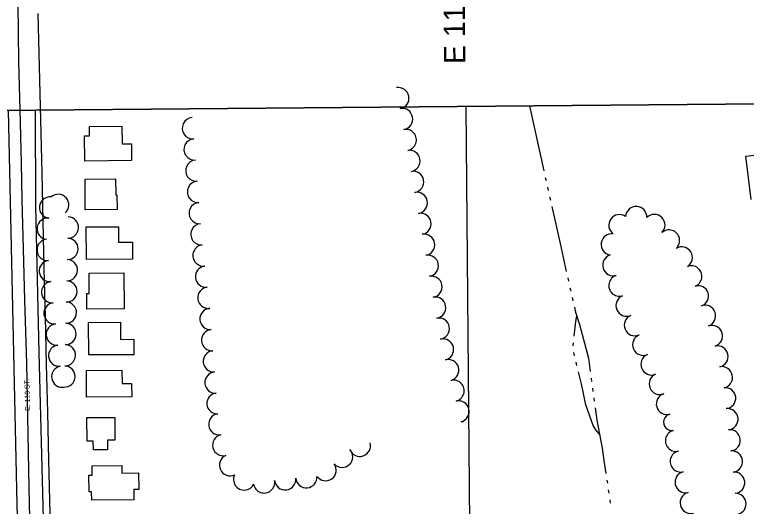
# Model space of a CAD drawing. Extents: x -2233 to 187241, y 4582 to 150524.
# Drawn here: x 111567 to 112255, y 59685 to 60147 of the extents above; entities that cross this region are included whole.
import ezdxf

# ---------------------------------------------------------------- set-up
doc = ezdxf.new("R2010")
doc.units = 0
for name, color, linetype in [('60', 7, 'Continuous'), ('BLDG', 7, 'Continuous'), ('GE_X_CL_2000', 7, 'Continuous'), ('GRID', 7, 'Continuous'), ('ROAD', 7, 'Continuous'), ('ROAD-NAME', 7, 'Continuous'), ('RW_X_Fee_RW', 7, 'Continuous'), ('TREES', 7, 'Continuous'), ('WATER', 7, 'Continuous')]:
    doc.layers.add(name, color=color, linetype=linetype)

msp = doc.modelspace()

# ---------------------------------------------------------------- linework, layer by layer
at = {"layer": '60'}
msp.add_line((109991.08, 60043.59), (114990.89, 60087.23), dxfattribs=at)
at = {"layer": 'BLDG'}
for points in [[(111668, 60025.85), (111676.84, 60025.92), (111676.98, 60010.16), (111632.95, 60009.77), (111632.74, 60033.38), (111637.51, 60033.42), (111637.44, 60042.34), (111667.86, 60042.61)], [(111661.95, 59993.12), (111662.08, 59978), (111663.18, 59978.01), (111663.3, 59964.29), (111633.4, 59964.03), (111633.15, 59992.87)], [(111664.49, 59948.11), (111664.62, 59933.45), (111677.76, 59933.57), (111677.9, 59917.55), (111634.64, 59917.17), (111634.37, 59947.85)], [(111634.91, 59870.71), (111634.79, 59885.28), (111637.15, 59885.3), (111636.98, 59904.32), (111669.71, 59904.61), (111670, 59871.02)], [(111666.41, 59858.38), (111666.5, 59842.18), (111678.99, 59842.26), (111679.08, 59827.79), (111636.69, 59827.54), (111636.5, 59858.2)], [(111667.87, 59813.31), (111667.98, 59800.68), (111677, 59800.76), (111677.11, 59788.23), (111634.63, 59787.86), (111634.41, 59813.02)], [(111661.07, 59768.87), (111661.26, 59747.6), (111654.19, 59747.54), (111654.27, 59738.42), (111641.03, 59738.3), (111640.96, 59746.5), (111635.18, 59746.45), (111634.99, 59768.64)], [(111667.66, 59723.58), (111667.72, 59716.62), (111683.55, 59716.76), (111683.69, 59701.02), (111678.92, 59700.98), (111679, 59691.35), (111639.43, 59691.01), (111639.36, 59699.02), (111636.95, 59698.99), (111636.82, 59714.48), (111639.92, 59714.51), (111639.84, 59723.34)]]:
    msp.add_lwpolyline(points, close=True, dxfattribs=at)
msp.add_lwpolyline([(112259.25, 59973.71), (112254.19, 60014.34), (112277.24, 60017.2)], dxfattribs=at)
at = {"layer": 'GE_X_CL_2000'}
msp.add_lwpolyline([(111569.9, 60158.24), (111570.61, 60102.99), (111571.86, 60058.16), (111573.19, 60008), (111573.92, 59973.34), (111575.04, 59927.2), (111576.39, 59879.05), (111578.02, 59819.9), (111580.22, 59703.14), (111581.06, 59673.72)], dxfattribs=at)
at = {"layer": 'GRID'}
for p, q in [((114990.89, 60087.23), (109991.08, 60043.59)), ((111991.01, 60061.05), (112014.55, 57363.38))]:
    msp.add_line(p, q, dxfattribs=at)
at = {"layer": 'ROAD'}
for points in [[(112373.84, 59543.05), (112169.26, 59540.64), (111865.76, 59535.63), (111696.22, 59533.79), (111617.75, 59532.75), (111611.79, 59532.85), (111605.74, 59534.54), (111600.24, 59539.44), (111597.13, 59546.59), (111596.48, 59553.13), (111594.73, 59649.67), (111590.02, 59829.84), (111586.81, 59967.47), (111586.75, 60057.52)], [(111560.77, 60057.29), (111565.27, 59857.69), (111569.07, 59687.36), (111572.65, 59560.5), (111572.74, 59550.42), (111572.13, 59544.98), (111568.5, 59539.66), (111565.4, 59536.03), (111560.09, 59533.08), (111555.19, 59531.83), (111315.1, 59528.88), (111302.11, 59529.03), (111295.33, 59532.69), (111289.41, 59538.81), (111287.06, 59545.89), (111286.58, 59562.68), (111284.3, 59638.89), (111281.06, 59774.49), (111275.94, 59946.05), (111275.78, 60054.81)]]:
    msp.add_lwpolyline(points, dxfattribs=at)
at = {"layer": 'RW_X_Fee_RW'}
msp.add_lwpolyline([(111603.05, 59562.65), (111600.32, 59678.59), (111599.14, 59728.58), (111598.08, 59773.57), (111597.02, 59818.56), (111595.96, 59863.54), (111594.9, 59908.53), (111593.84, 59953.52), (111592.78, 59998.51), (111591.6, 60048.49), (111590.42, 60098.48), (111589.25, 60148.47)], dxfattribs=at)
at = {"layer": 'TREES'}
for centre, radius, start, end in [((111927.62, 60068.96), 10, 280.17841, 100.17841), ((111931.15, 60049.27), 10, 280.17841, 100.17841), ((111734.54, 60040.62), 10, 94.58514, 274.58514), ((111934.68, 60029.59), 10, 280.14381, 100.14381), ((111736.14, 60020.68), 10, 94.58514, 274.58514), ((111938.16, 60009.89), 10, 279.90898, 99.90898), ((111737.74, 60000.74), 10, 94.58514, 274.58514), ((111941.6, 59990.19), 10, 279.90898, 99.90898), ((111739.34, 59980.81), 10, 94.58514, 274.58514), ((111600.23, 59966.11), 10, 83.91497, 263.91497), ((111607.92, 59968.57), 10, 311.51104, 131.51104), ((111945.04, 59970.49), 10, 279.90898, 99.90898), ((111740.94, 59960.87), 10, 94.58514, 274.58514), ((112151.23, 59957.16), 10, 357.22471, 177.22471), ((111598.11, 59946.22), 10, 83.91497, 263.91497), ((111617.13, 59947.27), 10, 268.63885, 88.63885), ((111948.49, 59950.79), 10, 279.90898, 99.90898), ((112135.48, 59949.47), 10, 54.7904, 234.7904), ((112168.31, 59949.62), 10, 315.14783, 135.14783), ((111742.54, 59940.94), 10, 94.58514, 274.58514), ((111951.93, 59931.09), 10, 279.90898, 99.90898), ((112128.3, 59931.4), 10, 81.89893, 261.89893), ((112182.06, 59935.11), 10, 311.77115, 131.77115), ((111598, 59926.32), 10, 95.45909, 275.45909), ((111616.66, 59927.27), 10, 268.63885, 88.63885), ((111744.5, 59921.04), 10, 96.69695, 276.69695), ((112194.03, 59919.18), 10, 302.0535, 122.0535), ((111955.37, 59911.39), 10, 279.90898, 99.90898), ((112129.72, 59911.91), 10, 106.43734, 286.43734), ((111600.05, 59906.43), 10, 96.30008, 276.30008), ((111616.18, 59907.28), 10, 268.63885, 88.63885), ((111746.83, 59901.18), 10, 96.68629, 276.68629), ((112202.96, 59901.39), 10, 291.28479, 111.28479), ((111958.81, 59891.68), 10, 279.90898, 99.90898), ((112135.43, 59892.74), 10, 106.74398, 286.74398), ((111602.25, 59886.55), 10, 96.30008, 276.30008), ((111615.71, 59887.28), 10, 268.63885, 88.63885), ((112209.67, 59882.94), 9.63, 288.64172, 108.64172), ((111749.16, 59881.31), 10, 96.68629, 276.68629), ((111962.25, 59871.98), 10, 279.90898, 99.90898), ((112142.21, 59873.96), 10, 112.96242, 292.96242), ((111604.44, 59866.67), 10, 96.30008, 276.30008), ((111615.23, 59867.29), 10, 268.63885, 88.63885), ((112215.95, 59864.34), 10, 288.64172, 108.64172), ((111751.1, 59861.41), 10, 94.47243, 274.47243), ((112150.02, 59855.55), 10, 112.96242, 292.96242), ((111965.69, 59852.28), 10, 279.90898, 99.90898), ((111606.64, 59846.79), 10, 96.30008, 276.30008), ((111614.76, 59847.29), 10, 268.63885, 88.63885), ((111752.66, 59841.47), 10, 94.47243, 274.47243), ((112222.34, 59845.39), 10, 288.64172, 108.64172), ((112157.82, 59837.13), 10, 112.96242, 292.96242), ((111614.28, 59827.3), 10, 268.63885, 88.63885), ((111969.66, 59832.69), 10, 282.97519, 102.97519), ((111608.83, 59826.91), 10, 96.30008, 276.30008), ((111754.22, 59821.53), 10, 94.47243, 274.47243), ((112227.63, 59826.14), 10, 282.07243, 102.07243), ((112165.62, 59818.71), 10, 112.96242, 292.96242), ((111611.75, 59807.14), 10, 100.48553, 280.48553), ((111613.8, 59807.3), 10, 268.63885, 88.63885), ((111974.55, 59813.3), 10, 285.31119, 105.31119), ((112231.8, 59806.58), 10, 282.00455, 102.00455), ((111755.78, 59801.59), 10, 94.47243, 274.47243), ((111979.55, 59793.93), 10, 283.67437, 103.67437), ((112173.42, 59800.3), 10, 112.96242, 292.96242), ((112234.92, 59786.96), 9.89, 276.01513, 96.01513), ((111757.32, 59781.98), 9.67, 94.47243, 274.47243), ((112180.13, 59781.49), 10, 106.29888, 286.29888), ((111984.28, 59774.5), 10, 283.66385, 103.66385), ((112237, 59767.18), 10, 276.01513, 96.01513), ((111759.42, 59762.44), 10, 97.73365, 277.73365), ((112184.68, 59764.31), 7.78, 102.95814, 282.95814), ((111986.81, 59754.78), 10, 78.19973, 90.99565), ((112188.67, 59746.98), 10, 102.95814, 282.95814), ((112239.1, 59747.29), 10, 276.01513, 96.01513), ((111763.07, 59742.8), 10, 103.36436, 283.36436), ((111891.53, 59742.21), 10, 200.88738, 16.78892), ((111874.81, 59731.89), 10, 222.49507, 42.49507), ((112193.16, 59727.49), 10, 102.95814, 282.95814), ((112241.19, 59727.4), 10, 276.01513, 96.01513), ((111769.53, 59723.97), 10, 114.49669, 294.49669), ((111859.31, 59719.31), 10, 215.60383, 35.60383), ((111782.67, 59710.5), 10, 154.09802, 334.09802), ((111841.21, 59712.66), 10, 184.76237, 4.76237), ((112197.74, 59708.02), 10, 103.51738, 283.51738), ((112243.29, 59707.51), 10, 276.01513, 96.01513), ((111801.53, 59707.82), 10, 189.69438, 9.69438), ((111821.32, 59710.67), 10, 186.69519, 6.69519), ((112202.51, 59688.6), 10, 104.08036, 284.08036), ((112244.52, 59687.57), 10, 271.05621, 91.05621)]:
    msp.add_arc(centre, radius, start, end, dxfattribs=at)
at = {"layer": 'WATER'}
for p, q in [((112050.87, 60061.57), (112064.46, 60000.57)), ((112065.81, 59994.47), (112066.5, 59991.41)), ((112067.85, 59985.32), (112068.53, 59982.26)), ((112069.89, 59976.16), (112070.57, 59973.11)), ((112086.93, 59899.92), (112087.61, 59896.86)), ((112088.98, 59890.77), (112089.66, 59887.72)), ((112091.04, 59881.62), (112091.72, 59878.57)), ((112091.98, 59836), (112092.33, 59839.11)), ((112093.38, 59826.84), (112092.65, 59829.88)), ((112095.57, 59817.72), (112094.84, 59820.76)), ((112108.91, 59805.74), (112109.33, 59802.64)), ((112110.15, 59796.44), (112110.57, 59793.34)), ((112111.4, 59787.15), (112111.82, 59784.05)), ((112123.68, 59710.02), (112124.13, 59706.94)), ((112125.04, 59700.74), (112125.49, 59697.66))]:
    msp.add_line(p, q, dxfattribs=at)
for points in [[(112071.93, 59967.01), (112079.62, 59932.45), (112085.55, 59906.02)], [(112093.09, 59872.47), (112094.17, 59867.66), (112098.08, 59856.3), (112106.39, 59824.45), (112108.08, 59811.93)], [(112093.02, 59845.32), (112094.56, 59859.11), (112095.36, 59864.2)], [(112116.82, 59753.07), (112113.33, 59757.29), (112110.73, 59761.34), (112104.02, 59780.81), (112099.7, 59800.43), (112099.41, 59801.76), (112097.04, 59811.64)], [(112112.65, 59777.86), (112114.21, 59766.29), (112119.38, 59740.08), (112120.96, 59728.39), (112122.76, 59716.2)], [(112126.41, 59691.48), (112126.44, 59691.25), (112126.82, 59688.38)]]:
    msp.add_lwpolyline(points, dxfattribs=at)

# ---------------------------------------------------------------- texts
at = {"layer": 'GRID'}
msp.add_text('E 112,000', height=20, rotation=90.5, dxfattribs=at).set_placement((111990.66, 60101.05))
at = {"layer": 'ROAD-NAME'}
msp.add_text('E. 119 ST.', height=4.68, rotation=91.28127, dxfattribs=at).set_placement((111581.53, 59775.13))

doc.saveas('drawing.dxf')
